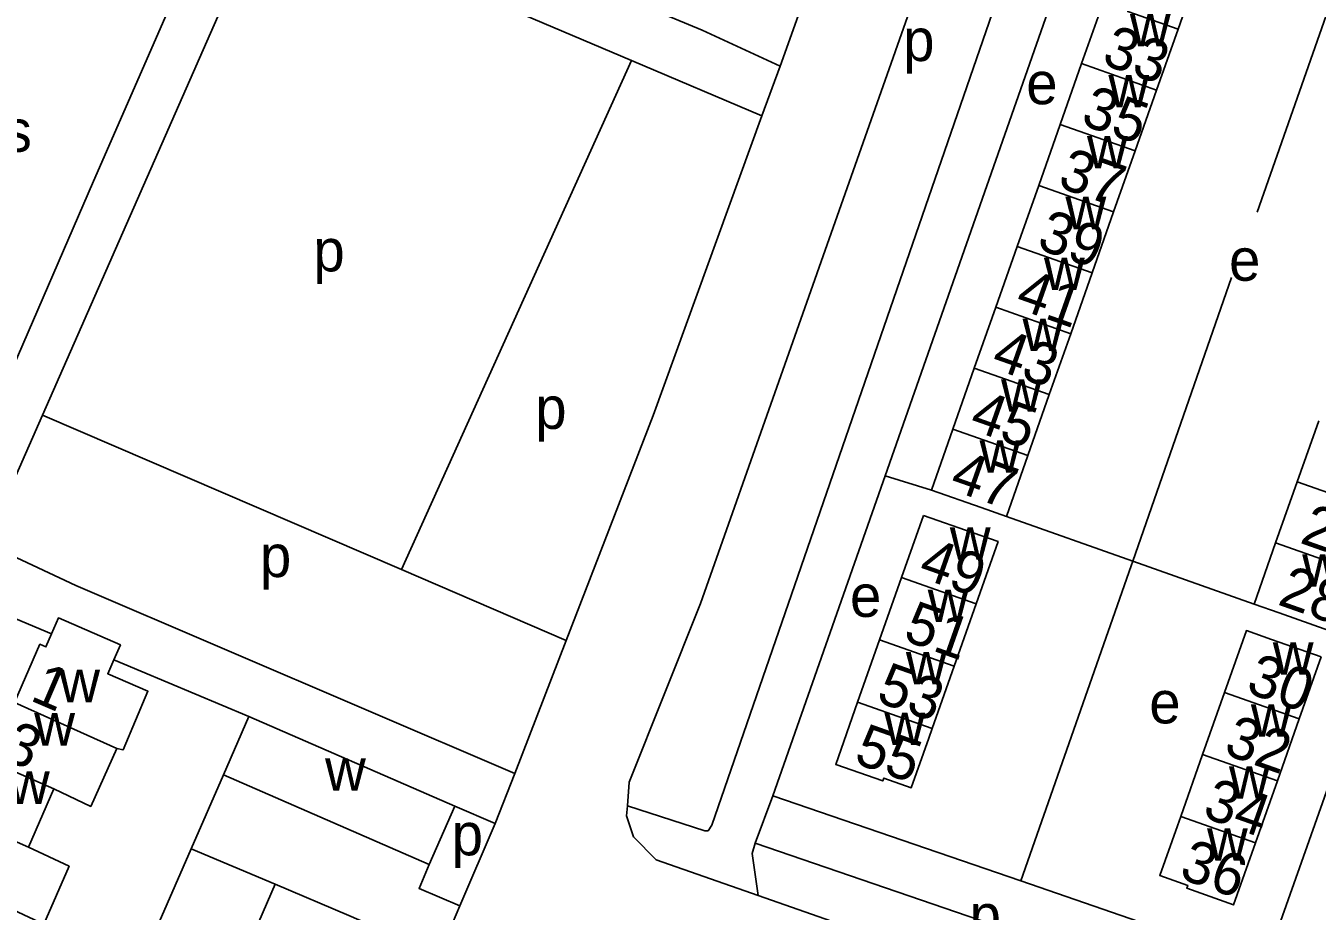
# Model space of a CAD drawing. Extents: x 162804 to 165059, y 381530 to 382901.
# Drawn here: x 163644.1 to 163766.6, y 381876.8 to 381960.8 of the extents above; entities that cross this region are included whole.
import ezdxf

# ---------------------------------------------------------------- set-up
doc = ezdxf.new("R2010")
doc.units = 0
for name, color, linetype in [('BLT_Basislijn', 7, 'Continuous'), ('BLT_Bebouwing', 7, 'Continuous'), ('BLT_Centroide', 7, 'Continuous'), ('BLT_Huisnummer', 7, 'Continuous'), ('BLT_Huisnummer_ tussenligend', 7, 'Continuous'), ('BLT_Onderverdeling_panden', 7, 'Continuous')]:
    doc.layers.add(name, color=color, linetype=linetype)

msp = doc.modelspace()

# ---------------------------------------------------------------- linework, layer by layer
at = {"layer": 'BLT_Basislijn'}
for p, q in [((163715.67, 381956.94), (163730.74, 381999.54)), ((163658.71, 381964.77), (163650.53, 381946.02)), ((163703.46, 381962.33), (163708.27, 381960.34)), ((163708.27, 381960.34), (163715.67, 381956.94)), ((163679.74, 381909.19), (163701.56, 381957.48)), ((163701.56, 381957.48), (163713.93, 381952.22)), ((163713.93, 381952.22), (163715.67, 381956.94)), ((163650.53, 381946.02), (163642.4, 381927.25)), ((163758.49, 381936.89), (163749.13, 381909.98)), ((163641.88, 381915.19), (163645.68, 381923.83)), ((163645.68, 381923.83), (163679.74, 381909.19)), ((163730.01, 381916.73), (163725.62, 381918.08)), ((163749.13, 381909.98), (163737.12, 381914.22)), ((163679.74, 381909.19), (163695.37, 381902.47)), ((163760.63, 381905.92), (163749.13, 381909.98)), ((163640.46, 381905.63), (163646.54, 381903.09)), ((163690.48, 381889.85), (163695.37, 381902.47)), ((163652.44, 381900.62), (163665.26, 381895.26)), ((163659.78, 381882.71), (163662.84, 381889.71)), ((163688.63, 381885.12), (163690.48, 381889.85)), ((163713.3, 381883.25), (163714.96, 381887.74)), ((163738.48, 381879.67), (163714.96, 381887.74)), ((163684.79, 381886.76), (163688.63, 381885.12)), ((163685.28, 381877.3), (163688.63, 381885.12)), ((163760.01, 381867.25), (163713.3, 381883.25)), ((163629.47, 381813.33), (163659.78, 381882.71)), ((163667.77, 381879.36), (163659.78, 381882.71)), ((163738.48, 381879.67), (163761.67, 381871.69)), ((163683.32, 381872.7), (163685.28, 381877.3))]:
    msp.add_line(p, q, dxfattribs=at)
for points in [[(163753.65, 382013.67), (163749.64, 382014.48), (163747.74, 382014.23), (163746.7, 382013.51), (163745.08, 382010.75), (163708.12, 381905.96), (163701.34, 381889.02), (163701.19, 381886.77)], [(163753.65, 382013.67), (163709.17, 381884.96), (163708.83, 381884.4), (163708.51, 381884.4), (163701.19, 381886.77)], [(163746.75, 381978.4), (163746.61, 381977.99), (163725.62, 381918.08)], [(163645.68, 381923.83), (163666.94, 381972.18), (163701.56, 381957.48)], [(163760.93, 381943.07), (163770.21, 381969.62), (163770.36, 381970.07)], [(163695.37, 381902.47), (163703.63, 381923.79), (163713.93, 381952.22)], [(163714.96, 381887.74), (163725.43, 381917.54), (163725.62, 381918.08)], [(163690.48, 381889.85), (163648.86, 381907.67), (163642.18, 381910.81)], [(163738.48, 381879.67), (163748.97, 381909.53), (163749.13, 381909.98)], [(163772.36, 381901.83), (163772.22, 381901.46), (163761.67, 381871.69)], [(163701.19, 381886.77), (163701.09, 381885.85), (163701.76, 381883.83), (163703.89, 381881.66), (163713.58, 381878.28)], [(163713.58, 381878.28), (163713, 381882.25), (163713.3, 381883.25)], [(163682.38, 381881.21), (163681.41, 381878.95), (163685.28, 381877.3)], [(163713.58, 381878.28), (163755.04, 381863.76), (163757.97, 381864.02), (163759.09, 381865.09), (163760.01, 381867.25)]]:
    msp.add_lwpolyline(points, dxfattribs=at)
at = {"layer": 'BLT_Bebouwing'}
for p, q in [((163755.45, 381966.22), (163753.41, 381960.44)), ((163744.26, 381957.17), (163746.3, 381962.95)), ((163753.41, 381960.44), (163751.38, 381954.66)), ((163742.23, 381951.39), (163744.26, 381957.17)), ((163751.38, 381954.66), (163749.34, 381948.89)), ((163740.19, 381945.62), (163742.23, 381951.39)), ((163749.34, 381948.89), (163747.3, 381943.11)), ((163738.15, 381939.84), (163740.19, 381945.62)), ((163747.3, 381943.11), (163745.27, 381937.33)), ((163736.12, 381934.06), (163738.15, 381939.84)), ((163745.27, 381937.33), (163743.23, 381931.55)), ((163734.08, 381928.29), (163736.12, 381934.06)), ((163743.23, 381931.55), (163741.19, 381925.78)), ((163732.04, 381922.51), (163734.08, 381928.29)), ((163741.19, 381925.78), (163739.15, 381920)), ((163730.01, 381916.73), (163732.04, 381922.51)), ((163766.76, 381923.29), (163764.72, 381917.5)), ((163739.15, 381920), (163737.12, 381914.22)), ((163764.72, 381917.5), (163762.67, 381911.72)), ((163727.17, 381908.43), (163729.26, 381914.33)), ((163762.67, 381911.72), (163760.63, 381905.92)), ((163725.09, 381902.52), (163727.17, 381908.43)), ((163734.25, 381905.93), (163732.17, 381900.03)), ((163723.01, 381896.62), (163725.09, 381902.52)), ((163766.98, 381900.9), (163764.91, 381895.02)), ((163732.17, 381900.03), (163730.08, 381894.12)), ((163755.74, 381891.65), (163757.81, 381897.53)), ((163665.26, 381895.26), (163662.84, 381889.71)), ((163684.79, 381886.76), (163665.26, 381895.26)), ((163764.91, 381895.02), (163762.83, 381889.15)), ((163753.66, 381885.78), (163755.74, 381891.65)), ((163646.76, 381888.4), (163644.36, 381882.87)), ((163762.83, 381889.15), (163760.76, 381883.27))]:
    msp.add_line(p, q, dxfattribs=at)
for points in [[(163737.12, 381914.22), (163734.72, 381915.07), (163730.01, 381916.73)], [(163729.26, 381914.33), (163733.97, 381912.67), (163736.33, 381911.84), (163734.25, 381905.93)], [(163760.63, 381905.92), (163763.01, 381905.08), (163767.7, 381903.42)], [(163652.44, 381900.62), (163653.07, 381902.05), (163647.2, 381904.6), (163646.54, 381903.09)], [(163646.54, 381903.09), (163646.01, 381901.86), (163645.44, 381902.11), (163643.04, 381896.58)], [(163757.81, 381897.53), (163759.89, 381903.4), (163762.27, 381902.57), (163766.98, 381900.9)], [(163652.74, 381892.22), (163653.32, 381892.08), (163655.69, 381897.65), (163651.87, 381899.31), (163652.44, 381900.62)], [(163730.08, 381894.12), (163729.76, 381893.21), (163728.1, 381888.49), (163725.49, 381889.41), (163725.4, 381889.14), (163720.93, 381890.71), (163723.01, 381896.62)], [(163652.74, 381892.22), (163650.26, 381886.72), (163646.76, 381888.4)], [(163662.84, 381889.71), (163682.38, 381881.21)], [(163682.38, 381881.21), (163684.79, 381886.76)], [(163760.76, 381883.27), (163758.68, 381877.39), (163754.23, 381878.96), (163754.33, 381879.24), (163751.68, 381880.17), (163753.35, 381884.89), (163753.66, 381885.78)], [(163644.36, 381882.87), (163648.21, 381881.06), (163645.82, 381875.56), (163641.95, 381877.35)], [(163667.77, 381879.36), (163665.39, 381873.89), (163669.83, 381871.79)], [(163678.98, 381874.55), (163674.74, 381876.38), (163667.77, 381879.36)]]:
    msp.add_lwpolyline(points, dxfattribs=at)
at = {"layer": 'BLT_Onderverdeling_panden'}
for p, q in [((163753.41, 381960.44), (163746.3, 381962.95)), ((163751.38, 381954.66), (163744.26, 381957.17)), ((163749.34, 381948.89), (163742.23, 381951.39)), ((163747.3, 381943.11), (163740.19, 381945.62)), ((163745.27, 381937.33), (163738.15, 381939.84)), ((163743.23, 381931.55), (163736.12, 381934.06)), ((163741.19, 381925.78), (163734.08, 381928.29)), ((163739.15, 381920), (163732.04, 381922.51)), ((163764.72, 381917.5), (163771.79, 381915.01)), ((163762.67, 381911.72), (163769.75, 381909.22)), ((163734.25, 381905.93), (163727.17, 381908.43)), ((163732.17, 381900.03), (163725.09, 381902.52)), ((163652.74, 381892.22), (163643.04, 381896.58)), ((163730.08, 381894.12), (163723.01, 381896.62)), ((163757.81, 381897.53), (163764.91, 381895.02)), ((163646.76, 381888.4), (163640.64, 381891.06)), ((163755.74, 381891.65), (163762.83, 381889.15)), ((163753.66, 381885.78), (163760.76, 381883.27)), ((163644.36, 381882.87), (163638.24, 381885.53))]:
    msp.add_line(p, q, dxfattribs=at)

# ---------------------------------------------------------------- texts
at = {"layer": 'BLT_Centroide'}
for s, p in [('w', (163748.84, 381958.81)), ('p', (163727.33, 381957.42)), ('e', (163739.01, 381953.32)), ('w', (163746.8, 381953.03)), ('s', (163642, 381948.81)), ('w', (163744.77, 381947.25)), ('w', (163742.73, 381941.47)), ('p', (163671.38, 381937.47)), ('e', (163758.25, 381936.58)), ('w', (163740.69, 381935.69)), ('w', (163738.66, 381929.91)), ('w', (163736.62, 381924.16)), ('p', (163692.43, 381922.53)), ('w', (163734.58, 381918.38)), ('w', (163731.76, 381910.12)), ('p', (163666.31, 381908.48)), ('w', (163765.19, 381907.56)), ('e', (163722.29, 381904.7)), ('w', (163729.66, 381904.22)), ('w', (163762.4, 381899.22)), ('w', (163727.59, 381898.31)), ('w', (163647.27, 381896.61)), ('e', (163750.68, 381894.6)), ('w', (163644.9, 381892.5)), ('w', (163725.55, 381892.56)), ('w', (163760.32, 381893.34)), ('w', (163672.49, 381888.22)), ('w', (163758.24, 381887.47)), ('w', (163642.5, 381886.97)), ('p', (163684.5, 381882.09)), ('w', (163756.16, 381881.59)), ('p', (163733.64, 381874.39))]:
    msp.add_text(s, height=4, dxfattribs=at).set_placement(p)
at = {"layer": 'BLT_Huisnummer'}
for s, rotation, p in [('33', 340.5751, (163746.04, 381957.16)), ('37', 340.5751, (163741.86, 381945.52)), ('41', 340.5751, (163737.83, 381934.05)), ('47', 340.5759, (163731.61, 381916.83)), ('49', 340.582, (163728.63, 381908.53)), ('28', 340.5466, (163762.74, 381905.91)), ('30', 340.5541, (163759.72, 381897.58)), ('1', 336.7537, (163644.39, 381896.83)), ('55', 340.5787, (163722.53, 381890.89)), ('36', 340.5485, (163753.39, 381879.96))]:
    msp.add_text(s, height=4, rotation=rotation, dxfattribs=at).set_placement(p)
at = {"layer": 'BLT_Huisnummer_ tussenligend'}
for s, rotation, p in [('35', 340.5751, (163744.05, 381951.44)), ('39', 340.5751, (163739.88, 381939.67)), ('43', 340.5751, (163735.55, 381928.36)), ('45', 340.5759, (163733.48, 381922.54)), ('26', 340.5466, (163764.85, 381911.76)), ('51', 340.582, (163727.2, 381902.53)), ('53', 340.582, (163724.65, 381896.7)), ('3', 336.7537, (163641.72, 381891.3)), ('32', 340.5541, (163757.61, 381891.73)), ('34', 340.5541, (163755.6, 381885.76))]:
    msp.add_text(s, height=4, rotation=rotation, dxfattribs=at).set_placement(p)

doc.saveas('drawing.dxf')
